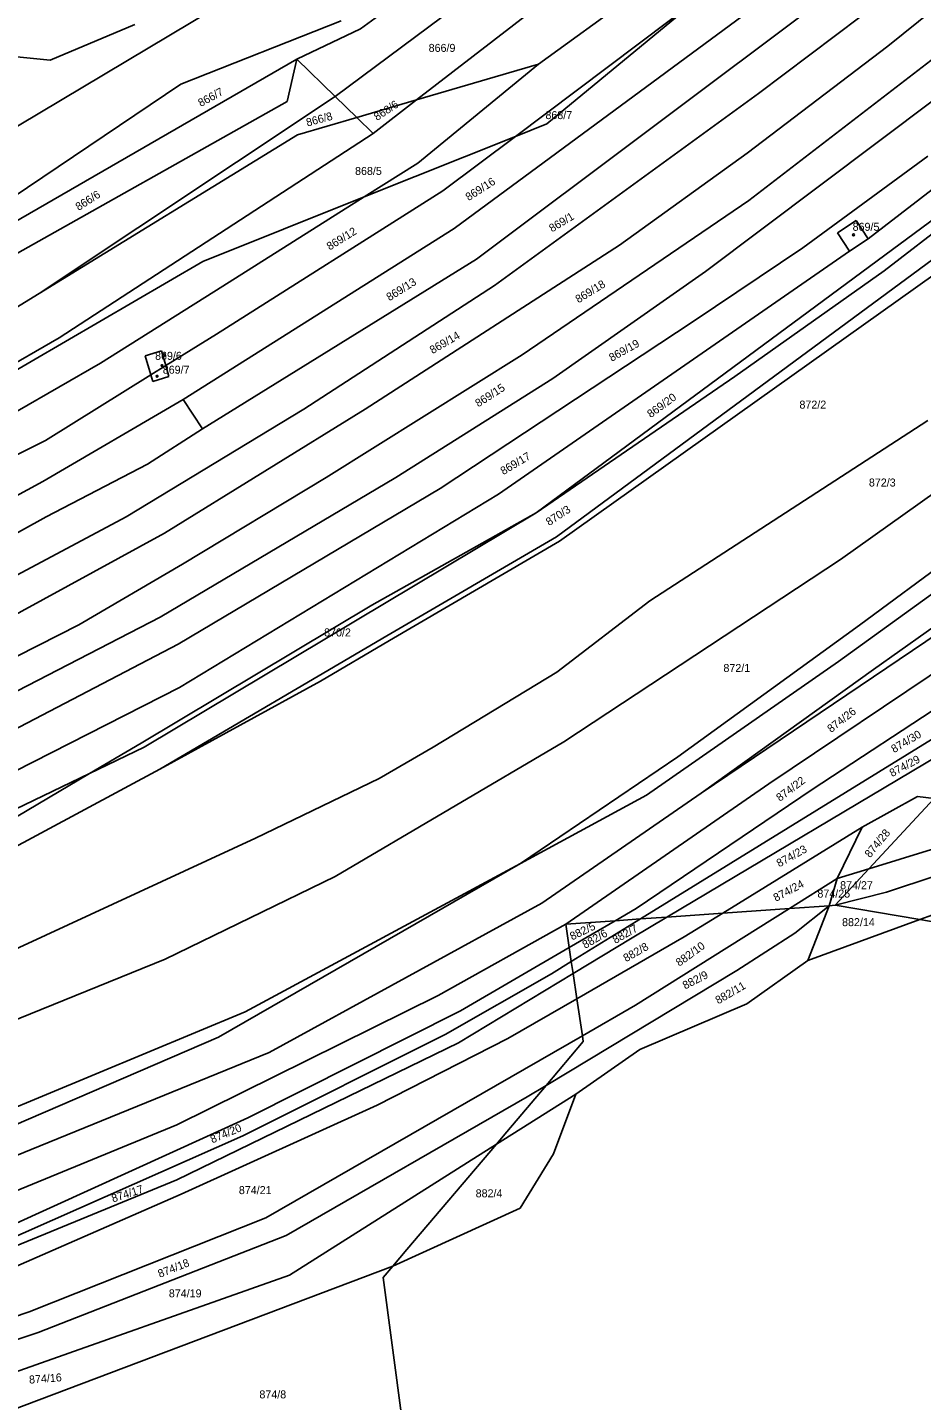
# Model space of a CAD drawing. Extents: x -563148 to -561712, y -1182311 to -1179502.
# Drawn here: x -562576.2 to -562408.6, y -1179961.9 to -1179704.6 of the extents above; entities that cross this region are included whole.
import ezdxf

# ---------------------------------------------------------------- set-up
doc = ezdxf.new("R2010")
doc.units = 0
for name, color, linetype in [('Vrstva 55', 7, 'Continuous'), ('Vrstva 56', 7, 'Continuous'), ('Vrstva 57', 7, 'Continuous')]:
    doc.layers.add(name, color=color, linetype=linetype)

msp = doc.modelspace()

# ---------------------------------------------------------------- linework, layer by layer
at = {"layer": 'Vrstva 55'}
for p, q in [((-562518.51, -1179717.48), (-562420.25, -1179644.35)), ((-562513.78, -1179704.82), (-562440.83, -1179651.65)), ((-562408.44, -1179659.18), (-562480.38, -1179711.45)), ((-562503.24, -1179718.15), (-562429.52, -1179661.17)), ((-562496.21, -1179742.23), (-562390.08, -1179664.03)), ((-562492.04, -1179747.96), (-562383.14, -1179666.38)), ((-562376.89, -1179670.03), (-562439.16, -1179716.94)), ((-562414.93, -1179708.08), (-562372.83, -1179674.14)), ((-562598.9, -1179735.51), (-562527.52, -1179692.89)), ((-562484.72, -1179724.98), (-562450.05, -1179698.9)), ((-562478.81, -1179722.61), (-562450.05, -1179698.9)), ((-562394.61, -1179701.31), (-562440.98, -1179737.01)), ((-562571.92, -1179710.67), (-562556.04, -1179704.04)), ((-562547.45, -1179715.18), (-562517.36, -1179703.32)), ((-562525.69, -1179710.49), (-562513.78, -1179704.82)), ((-562441.24, -1179728.15), (-562414.93, -1179708.08)), ((-562596.17, -1179751.15), (-562525.69, -1179710.49)), ((-562582.26, -1179709.64), (-562571.92, -1179710.67)), ((-562525.69, -1179710.49), (-562527.52, -1179718.44)), ((-562525.69, -1179710.49), (-562518.51, -1179717.48)), ((-562503.24, -1179718.15), (-562480.38, -1179711.45)), ((-562502.99, -1179729.98), (-562480.38, -1179711.45)), ((-562588.48, -1179742.81), (-562547.45, -1179715.18)), ((-562527.52, -1179718.44), (-562581.06, -1179748.54)), ((-562574.01, -1179754.42), (-562518.51, -1179717.48)), ((-562518.51, -1179717.48), (-562514.45, -1179721.44)), ((-562514.45, -1179721.44), (-562503.24, -1179718.15)), ((-562511.37, -1179724.43), (-562503.24, -1179718.15)), ((-562439.16, -1179716.94), (-562488.66, -1179752.91)), ((-562449.06, -1179750.31), (-562406.07, -1179717.99)), ((-562525.58, -1179724.7), (-562514.45, -1179721.44)), ((-562514.45, -1179721.44), (-562511.37, -1179724.43)), ((-562484.72, -1179724.98), (-562478.81, -1179722.61)), ((-562418.6, -1179744.19), (-562390.18, -1179722.26)), ((-562525.58, -1179724.7), (-562574.01, -1179754.42)), ((-562511.37, -1179724.43), (-562570.24, -1179762.75)), ((-562513.08, -1179736.33), (-562484.72, -1179724.98)), ((-562498.3, -1179735.19), (-562484.72, -1179724.98)), ((-562465.21, -1179745.35), (-562441.24, -1179728.15)), ((-562407.37, -1179728.67), (-562430.82, -1179745.87)), ((-562385.23, -1179726.71), (-562415.58, -1179750.17)), ((-562513.08, -1179736.33), (-562502.99, -1179729.98)), ((-562543.31, -1179748.44), (-562513.08, -1179736.33)), ((-562540.76, -1179762.03), (-562498.3, -1179735.19)), ((-562539.59, -1179753.03), (-562513.08, -1179736.33)), ((-562398.48, -1179734.67), (-562480.81, -1179795.55)), ((-562440.98, -1179737.01), (-562483.45, -1179765.94)), ((-562393.96, -1179738.81), (-562477.04, -1179800.04)), ((-562386.4, -1179736.74), (-562476.45, -1179800.84)), ((-562424.32, -1179743.05), (-562420.86, -1179740.77)), ((-562420.86, -1179740.77), (-562418.6, -1179744.19)), ((-562547.01, -1179774.27), (-562496.21, -1179742.23)), ((-562422.07, -1179746.47), (-562424.32, -1179743.05)), ((-562418.6, -1179744.19), (-562422.07, -1179746.47)), ((-562512.89, -1179776.11), (-562465.21, -1179745.35)), ((-562487.88, -1179792.01), (-562422.07, -1179746.47)), ((-562430.82, -1179745.87), (-562451.4, -1179759.69)), ((-562543.31, -1179748.44), (-562590.73, -1179775.97)), ((-562543.36, -1179779.75), (-562492.04, -1179747.96)), ((-562477.72, -1179770.37), (-562449.06, -1179750.31)), ((-562415.58, -1179750.17), (-562443.58, -1179769.98)), ((-562574.01, -1179754.42), (-562593.86, -1179766.61)), ((-562562.51, -1179767.5), (-562539.59, -1179753.03)), ((-562488.66, -1179752.91), (-562524.35, -1179776.11)), ((-562550.26, -1179767.94), (-562540.76, -1179762.03)), ((-562451.4, -1179759.69), (-562498.82, -1179790.96)), ((-562584, -1179770.62), (-562570.24, -1179762.75)), ((-562554.11, -1179766.08), (-562551.05, -1179765.19)), ((-562554.11, -1179766.08), (-562553.07, -1179769.69)), ((-562551.05, -1179765.19), (-562550.87, -1179765.81)), ((-562550.87, -1179765.81), (-562550.44, -1179765.69)), ((-562550.32, -1179766.11), (-562550.75, -1179766.24)), ((-562550.75, -1179766.24), (-562550.26, -1179767.94)), ((-562550.44, -1179765.69), (-562550.32, -1179766.11)), ((-562483.45, -1179765.94), (-562520.18, -1179788.88)), ((-562578.14, -1179776.49), (-562562.51, -1179767.5)), ((-562572.8, -1179781.96), (-562553.07, -1179769.69)), ((-562553.07, -1179769.69), (-562550.26, -1179767.94)), ((-562553.07, -1179769.69), (-562552.72, -1179770.9)), ((-562549.67, -1179769.95), (-562552.72, -1179770.9)), ((-562550.26, -1179767.94), (-562549.67, -1179769.95)), ((-562507.15, -1179788.88), (-562477.72, -1179770.37)), ((-562443.58, -1179769.98), (-562480.81, -1179795.55)), ((-562573.32, -1179789.65), (-562547.01, -1179774.27)), ((-562547.01, -1179774.27), (-562543.36, -1179779.75)), ((-562524.35, -1179776.11), (-562557.69, -1179796.3)), ((-562550.52, -1179799.3), (-562512.89, -1179776.11)), ((-562543.36, -1179779.75), (-562553.66, -1179786.39)), ((-562459.54, -1179811.99), (-562407.37, -1179778.19)), ((-562642.31, -1179816.48), (-562572.8, -1179781.96)), ((-562390.44, -1179780.54), (-562423.79, -1179804.26)), ((-562553.66, -1179786.39), (-562572.67, -1179796.3)), ((-562641.45, -1179826.4), (-562573.32, -1179789.65)), ((-562551.31, -1179815.07), (-562507.15, -1179788.88)), ((-562520.18, -1179788.88), (-562547.14, -1179805.16)), ((-562498.82, -1179790.96), (-562547.92, -1179820.15)), ((-562547.66, -1179828.23), (-562487.88, -1179792.01)), ((-562381.7, -1179792.64), (-562424.16, -1179823.4)), ((-562554.3, -1179839.44), (-562480.81, -1179795.55)), ((-562480.81, -1179795.55), (-562511.63, -1179812.81)), ((-562618.78, -1179828.75), (-562557.69, -1179796.3)), ((-562612.4, -1179817.93), (-562572.67, -1179796.3)), ((-562392.48, -1179796.07), (-562420.23, -1179816.57)), ((-562593.12, -1179822.62), (-562550.52, -1179799.3)), ((-562477.04, -1179800.04), (-562508.8, -1179818.58)), ((-562508.3, -1179819.44), (-562476.45, -1179800.84)), ((-562566.55, -1179816.5), (-562547.14, -1179805.16)), ((-562423.79, -1179804.26), (-562475.63, -1179838.4)), ((-562417.57, -1179824.87), (-562388.02, -1179803.91)), ((-562449.89, -1179848.03), (-562392.89, -1179809.58)), ((-562381.5, -1179808.86), (-562437.18, -1179846.33)), ((-562511.63, -1179812.81), (-562554.9, -1179838.66)), ((-562476.94, -1179825.36), (-562459.54, -1179811.99)), ((-562429.1, -1179847.38), (-562377.63, -1179813.55)), ((-562585.44, -1179832.66), (-562551.31, -1179815.07)), ((-562608.1, -1179837.61), (-562566.55, -1179816.5)), ((-562508.8, -1179818.58), (-562551.37, -1179843.58)), ((-562420.23, -1179816.57), (-562454.26, -1179841.24)), ((-562584.52, -1179839.17), (-562547.92, -1179820.15)), ((-562521.23, -1179827.04), (-562508.3, -1179819.44)), ((-562424.16, -1179823.4), (-562460.12, -1179848.42)), ((-562500.12, -1179839.43), (-562476.94, -1179825.36)), ((-562449.89, -1179848.03), (-562417.57, -1179824.87)), ((-562585.04, -1179847.25), (-562547.66, -1179828.23)), ((-562521.23, -1179827.04), (-562551.37, -1179843.58)), ((-562564.55, -1179844.37), (-562554.9, -1179838.66)), ((-562564.55, -1179844.37), (-562554.3, -1179839.44)), ((-562518.49, -1179863.67), (-562475.63, -1179838.4)), ((-562510.28, -1179845.3), (-562500.12, -1179839.43)), ((-562461.26, -1179871.61), (-562405.92, -1179837.47)), ((-562456.35, -1179871.27), (-562402.39, -1179839.17)), ((-562454.26, -1179841.24), (-562483.75, -1179861.2)), ((-562605.55, -1179864.1), (-562564.55, -1179844.37)), ((-562583.01, -1179855.3), (-562564.55, -1179844.37)), ((-562551.37, -1179843.58), (-562580.28, -1179859.12)), ((-562533.47, -1179856.5), (-562510.28, -1179845.3)), ((-562475.29, -1179872.6), (-562437.18, -1179846.33)), ((-562460.12, -1179848.42), (-562483.75, -1179861.2)), ((-562479.79, -1179868.68), (-562449.89, -1179848.03)), ((-562462.06, -1179869.66), (-562429.1, -1179847.38)), ((-562419.73, -1179854.41), (-562409.31, -1179848.68)), ((-562418.44, -1179862.21), (-562406.22, -1179849.04)), ((-562409.31, -1179848.68), (-562406.22, -1179849.04)), ((-562445.84, -1179870.53), (-562419.73, -1179854.41)), ((-562419.73, -1179854.41), (-562424.42, -1179864.06)), ((-562613.28, -1179893.4), (-562533.47, -1179856.5)), ((-562418.44, -1179862.21), (-562406.7, -1179858.58)), ((-562483.75, -1179861.2), (-562540.35, -1179893.77)), ((-562483.75, -1179861.2), (-562535.37, -1179889.03)), ((-562424.79, -1179869.05), (-562418.44, -1179862.21)), ((-562424.42, -1179864.06), (-562418.44, -1179862.21)), ((-562550.4, -1179879.18), (-562518.49, -1179863.67)), ((-562433.33, -1179869.65), (-562424.42, -1179864.06)), ((-562425.9, -1179869.13), (-562424.42, -1179864.06)), ((-562415.13, -1179866.6), (-562405.92, -1179863.53)), ((-562424.79, -1179869.05), (-562415.13, -1179866.6)), ((-562530.85, -1179896.65), (-562479.79, -1179868.68)), ((-562465.99, -1179871.95), (-562462.06, -1179869.66)), ((-562462.2, -1179887.77), (-562433.33, -1179869.65)), ((-562445.84, -1179870.53), (-562433.33, -1179869.65)), ((-562433.33, -1179869.65), (-562425.9, -1179869.13)), ((-562432.36, -1179874.26), (-562425.9, -1179869.13)), ((-562425.9, -1179869.13), (-562429.89, -1179879.43)), ((-562425.9, -1179869.13), (-562424.79, -1179869.05)), ((-562408.89, -1179871.73), (-562424.79, -1179869.05)), ((-562499.19, -1179885.95), (-562475.29, -1179872.6)), ((-562475.29, -1179872.6), (-562465.99, -1179871.95)), ((-562475.29, -1179872.6), (-562474.64, -1179876.97)), ((-562474.64, -1179876.97), (-562465.99, -1179871.95)), ((-562474.24, -1179879.62), (-562461.26, -1179871.61)), ((-562465.99, -1179871.95), (-562461.26, -1179871.61)), ((-562462.84, -1179875.13), (-562456.35, -1179871.27)), ((-562461.26, -1179871.61), (-562456.35, -1179871.27)), ((-562456.35, -1179871.27), (-562445.84, -1179870.53)), ((-562453.08, -1179875), (-562445.84, -1179870.53)), ((-562429.89, -1179879.43), (-562408.89, -1179871.73)), ((-562408.89, -1179871.73), (-562406.44, -1179870.83)), ((-562408.89, -1179871.73), (-562392.9, -1179874.42)), ((-562473.91, -1179881.82), (-562462.84, -1179875.13)), ((-562473.2, -1179886.57), (-562453.08, -1179875)), ((-562432.36, -1179874.26), (-562443.18, -1179881.26)), ((-562495.02, -1179888.82), (-562474.64, -1179876.97)), ((-562474.64, -1179876.97), (-562474.24, -1179879.62)), ((-562609.82, -1179903.23), (-562550.4, -1179879.18)), ((-562477.95, -1179881.91), (-562474.24, -1179879.62)), ((-562474.24, -1179879.62), (-562473.91, -1179881.82)), ((-562429.89, -1179879.43), (-562441.35, -1179887.51)), ((-562477.95, -1179881.91), (-562497.88, -1179893.25)), ((-562495.41, -1179894.81), (-562473.91, -1179881.82)), ((-562478.97, -1179902.84), (-562443.18, -1179881.26)), ((-562473.91, -1179881.82), (-562473.2, -1179886.57)), ((-562548.17, -1179910.19), (-562499.19, -1179885.95)), ((-562486.16, -1179894.03), (-562473.2, -1179886.57)), ((-562473.2, -1179886.57), (-562472.16, -1179893.5)), ((-562472.16, -1179893.5), (-562462.2, -1179887.77)), ((-562441.35, -1179887.51), (-562461.41, -1179896.11)), ((-562535.37, -1179889.03), (-562604.71, -1179917.83)), ((-562534.88, -1179908.89), (-562495.02, -1179888.82)), ((-562497.88, -1179893.25), (-562535.79, -1179912.28)), ((-562540.35, -1179893.77), (-562595.33, -1179917.49)), ((-562548.17, -1179920.49), (-562495.41, -1179894.81)), ((-562531.5, -1179927.65), (-562472.16, -1179893.5)), ((-562510.65, -1179906.54), (-562486.16, -1179894.03)), ((-562478.97, -1179902.84), (-562471.99, -1179894.61)), ((-562472.16, -1179893.5), (-562471.99, -1179894.61)), ((-562601.63, -1179925.48), (-562530.85, -1179896.65)), ((-562461.41, -1179896.11), (-562473.4, -1179904.45)), ((-562486.3, -1179911.48), (-562478.97, -1179902.84)), ((-562482.52, -1179904.98), (-562478.97, -1179902.84)), ((-562527.7, -1179930.96), (-562482.52, -1179904.98)), ((-562488.27, -1179913.8), (-562473.4, -1179904.45)), ((-562473.4, -1179904.45), (-562477.57, -1179915.66)), ((-562578.91, -1179928.95), (-562534.88, -1179908.89)), ((-562547.39, -1179923.22), (-562510.65, -1179906.54)), ((-562590.12, -1179927.39), (-562548.17, -1179910.19)), ((-562488.27, -1179913.8), (-562486.3, -1179911.48)), ((-562535.79, -1179912.28), (-562582.16, -1179932.74)), ((-562505.05, -1179933.57), (-562488.27, -1179913.8)), ((-562493.72, -1179917.23), (-562488.27, -1179913.8)), ((-562477.57, -1179915.66), (-562483.82, -1179925.83)), ((-562493.72, -1179917.23), (-562527.07, -1179938.34)), ((-562583.99, -1179935.21), (-562548.17, -1179920.49)), ((-562578.39, -1179936.77), (-562547.39, -1179923.22)), ((-562483.82, -1179925.83), (-562507.68, -1179936.66)), ((-562575.89, -1179945.21), (-562531.5, -1179927.65)), ((-562527.7, -1179930.96), (-562574.17, -1179949.12)), ((-562507.68, -1179936.66), (-562505.05, -1179933.57)), ((-562622.8, -1179980.18), (-562507.68, -1179936.66)), ((-562509.48, -1179938.79), (-562507.68, -1179936.66)), ((-562527.07, -1179938.34), (-562625.22, -1179973.02)), ((-562506.03, -1179965.07), (-562509.48, -1179938.79)), ((-562575.89, -1179945.21), (-562619.28, -1179960.3)), ((-562574.17, -1179949.12), (-562627.35, -1179966.72))]:
    msp.add_line(p, q, dxfattribs=at)
at = {"layer": 'Vrstva 56'}
msp.add_line((-562550.87, -1179765.81), (-562550.75, -1179766.24), dxfattribs=at)
at = {"layer": 'Vrstva 57'}
for centre in [(-562421.33, -1179743.44), (-562551.9, -1179769.93), (-562550.97, -1179767.94)]:
    msp.add_circle(centre, 0.175, dxfattribs=at)

# ---------------------------------------------------------------- texts
for s, p in [('866/9', (-562500.98, -1179709.15)), ('868/7', (-562479.09, -1179721.74)), ('868/5', (-562514.78, -1179732.21)), ('869/5', (-562421.5, -1179742.67)), ('869/6', (-562552.27, -1179766.85)), ('869/7', (-562550.83, -1179769.45)), ('872/2', (-562431.47, -1179775.99)), ('872/3', (-562418.45, -1179790.59)), ('870/2', (-562520.58, -1179818.68)), ('872/1', (-562445.72, -1179825.35)), ('874/27', (-562423.84, -1179866.04)), ('874/25', (-562428.1, -1179867.62)), ('882/14', (-562423.48, -1179872.97)), ('874/21', (-562536.56, -1179923.18)), ('882/4', (-562492.17, -1179923.78)), ('874/19', (-562549.69, -1179942.52)), ('874/8', (-562532.71, -1179961.46))]:
    msp.add_text(s, height=1.5, dxfattribs=at).set_placement(p)
for s, rotation, p in [('866/7', 28.5805, (-562543.71, -1179719.49)), ('868/6', 33.2749, (-562510.66, -1179722.11)), ('866/8', 15.1689, (-562523.72, -1179723.14)), ('869/16', 32.6458, (-562493.48, -1179737.13)), ('866/6', 32.4518, (-562566.6, -1179738.96)), ('869/1', 31.1879, (-562477.85, -1179742.99)), ('869/12', 31.7194, (-562519.53, -1179746.38)), ('869/13', 32.0683, (-562508.33, -1179755.89)), ('869/18', 31.6015, (-562472.9, -1179756.28)), ('869/14', 30.2328, (-562500.25, -1179765.8)), ('869/19', 29.3333, (-562466.65, -1179767.23)), ('869/15', 32.9253, (-562491.66, -1179775.78)), ('869/20', 35.9931, (-562459.35, -1179777.79)), ('869/17', 30.8014, (-562486.97, -1179788.47)), ('870/3', 33.3901, (-562478.4, -1179798.02)), ('874/26', 38.0802, (-562425.53, -1179836.79)), ('874/30', 30.5684, (-562413.74, -1179840.56)), ('874/29', 28.0942, (-562414.1, -1179845.06)), ('874/22', 36.9212, (-562435.14, -1179849.69)), ('874/28', 50.4038, (-562418.24, -1179860.27)), ('874/23', 29.0917, (-562435.26, -1179861.97)), ('874/24', 28.1634, (-562435.87, -1179868.42)), ('882/5', 25.654, (-562474.07, -1179875.65)), ('882/7', 29.9016, (-562465.98, -1179876.32)), ('882/6', 29.8679, (-562471.64, -1179877.24)), ('882/8', 29.7449, (-562463.96, -1179879.74)), ('882/10', 36.0614, (-562453.99, -1179880.59)), ('882/9', 27.0251, (-562452.9, -1179884.85)), ('882/11', 30.2503, (-562446.69, -1179887.64)), ('874/20', 22.8336, (-562541.54, -1179913.69)), ('874/17', 18.1418, (-562560.15, -1179924.76)), ('874/18', 21.5607, (-562551.39, -1179938.87)), ('874/16', 4.2653, (-562575.84, -1179958.7))]:
    msp.add_text(s, height=1.5, rotation=rotation, dxfattribs=at).set_placement(p)

doc.saveas('drawing.dxf')
